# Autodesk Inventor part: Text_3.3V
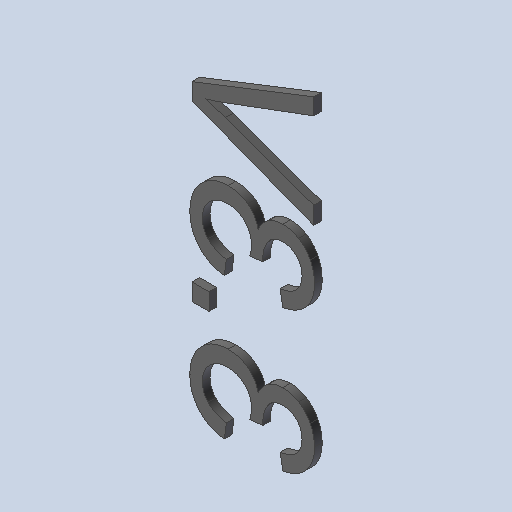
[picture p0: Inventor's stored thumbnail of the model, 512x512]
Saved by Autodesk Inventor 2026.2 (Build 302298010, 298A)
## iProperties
Created: 2026-10
Part Number: Text_3.3V
Material: Générique
Document SubType Name: Modeling
Designer: mel
Density: 1 g/cm^3
Appearance: Par défaut
Author: mel
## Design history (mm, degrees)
feature "Base1"
feature "Base2"
feature "Base3"
feature "Base4"
node "Solide1"
node "Solide2"
node "Solide3"
node "Solide4"
